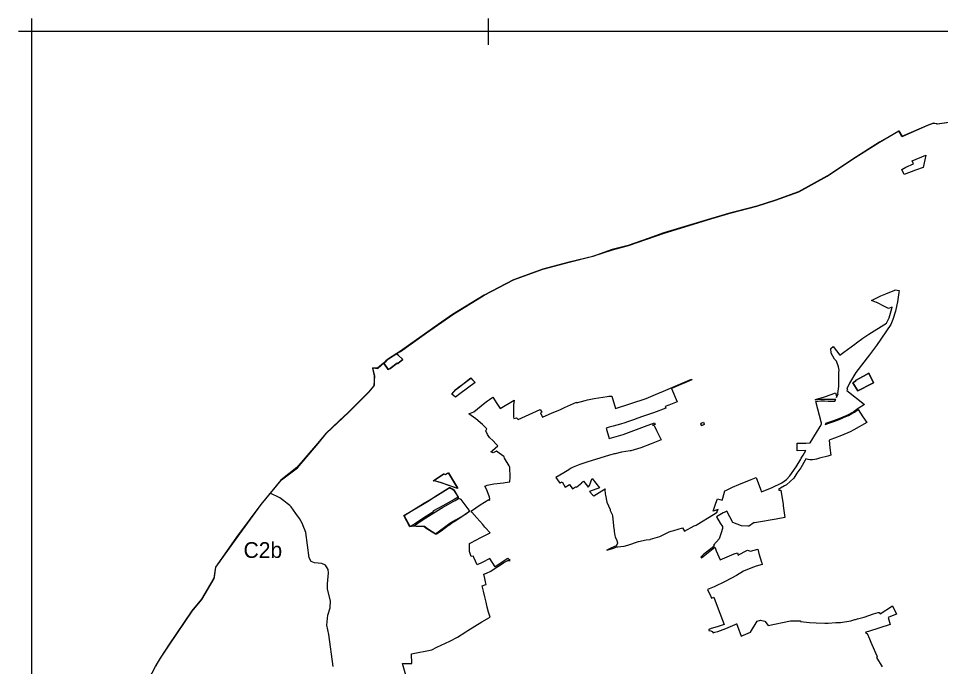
# Model space of a CAD drawing. Extents: x -478490 to -472450, y -1118050 to -1109550.
# Drawn here: x -478490 to -474975, y -1112018 to -1109550 of the extents above; entities that cross this region are included whole.
import ezdxf

# ---------------------------------------------------------------- set-up
doc = ezdxf.new("R2010")
doc.units = 0
for name, color, linetype in [('hranice kú', 7, 'Continuous'), ('Implicitní', 7, 'Continuous'), ('ObPÚ', 7, 'Continuous')]:
    doc.layers.add(name, color=color, linetype=linetype)

msp = doc.modelspace()

# ---------------------------------------------------------------- linework, layer by layer
at = {"layer": 'hranice kú'}
for p, q in [((-475002.4, -1109948.5), (-475022.9, -1109956.5)), ((-474987.2, -1109952.5), (-475002.4, -1109948.5)), ((-474886, -1109937.7), (-474987.2, -1109952.5)), ((-475134, -1109979), (-475207.8, -1110021.5)), ((-475122.4, -1109999.6), (-475134, -1109979)), ((-475022.9, -1109956.5), (-475122.4, -1109999.6)), ((-475207.8, -1110021.5), (-475309.6, -1110086.2)), ((-475309.6, -1110086.2), (-475401.1, -1110146.7)), ((-475408.2, -1110151.3), (-475516.2, -1110210.6)), ((-475401.1, -1110146.7), (-475408.2, -1110151.3)), ((-475516.2, -1110210.6), (-475603.8, -1110242.4)), ((-475675.9, -1110264.8), (-475748.8, -1110283.6)), ((-475603.8, -1110242.4), (-475675.9, -1110264.8)), ((-475774.2, -1110290.1), (-475851.9, -1110313.6)), ((-475748.8, -1110283.6), (-475774.2, -1110290.1)), ((-475851.9, -1110313.6), (-476030.1, -1110367.2)), ((-476030.1, -1110367.2), (-476089.1, -1110387.7)), ((-476089.1, -1110387.7), (-476165.8, -1110414.4)), ((-476226.9, -1110430.6), (-476300.5, -1110456.1)), ((-476165.8, -1110414.4), (-476226.9, -1110430.6)), ((-476390.6, -1110478.9), (-476491.3, -1110505.4)), ((-476300.5, -1110456.1), (-476390.6, -1110478.9)), ((-476491.3, -1110505.4), (-476602.9, -1110545.8)), ((-476602.9, -1110545.8), (-476714.7, -1110603.6)), ((-476714.7, -1110603.6), (-476835.3, -1110677.2)), ((-476835.3, -1110677.2), (-476889.8, -1110715.9)), ((-476889.8, -1110715.9), (-477034.1, -1110817.7)), ((-477047.8, -1110826.2), (-477079.5, -1110846.1)), ((-477034.1, -1110817.7), (-477047.8, -1110826.2)), ((-477098.4, -1110862.6), (-477121, -1110882.3)), ((-477089.2, -1110854.5), (-477098.4, -1110862.6)), ((-477079.5, -1110846.1), (-477089.2, -1110854.5)), ((-477121, -1110882.3), (-477141, -1110882)), ((-477141, -1110882), (-477133.6, -1110911.5)), ((-477134.2, -1110929.3), (-477134.7, -1110947.1)), ((-477133.6, -1110911.5), (-477134.2, -1110929.3)), ((-477155, -1110972.4), (-477210.7, -1111027.9)), ((-477142.3, -1110956.6), (-477155, -1110972.4)), ((-477134.7, -1110947.1), (-477142.3, -1110956.6)), ((-477216.6, -1111033.9), (-477229.4, -1111046.9)), ((-477214.6, -1111031.9), (-477216.6, -1111033.9)), ((-477210.7, -1111027.9), (-477214.6, -1111031.9)), ((-477233.1, -1111050.4), (-477267, -1111082.3)), ((-477229.4, -1111046.9), (-477233.1, -1111050.4)), ((-477267, -1111082.3), (-477317.9, -1111130.4)), ((-477317.9, -1111130.4), (-477350, -1111169.3)), ((-477350, -1111169.3), (-477428.5, -1111260.9)), ((-477428.5, -1111260.9), (-477490.1, -1111308.2)), ((-477490.1, -1111308.2), (-477566.2, -1111401.8)), ((-477566.2, -1111401.8), (-477658.2, -1111526.7)), ((-477658.2, -1111526.7), (-477738.5, -1111640.6)), ((-477738.5, -1111640.6), (-477743.9, -1111676.8)), ((-477745.7, -1111682.6), (-477792.7, -1111763.5)), ((-477743.9, -1111676.8), (-477745.7, -1111682.6)), ((-477792.7, -1111763.5), (-477829.2, -1111807.1)), ((-477829.2, -1111807.1), (-477917, -1111937.1)), ((-477917, -1111937.1), (-477949.4, -1111986.8)), ((-477949.4, -1111986.8), (-477967.8, -1112018.8))]:
    msp.add_line(p, q, dxfattribs=at)
at = {"layer": 'Implicitní'}
for p, q in [((-478440.1, -1109550.1), (-478440.1, -1109650.1)), ((-478440.1, -1109550.1), (-478440.1, -1109650.1)), ((-478440.1, -1109550.1), (-478440.1, -1109650.1)), ((-478440.1, -1109550.1), (-478440.1, -1109650.1)), ((-478440.1, -1109550.1), (-478440.1, -1109650.1)), ((-478440.1, -1109550.1), (-478440.1, -1109650.1)), ((-478440.1, -1109550.1), (-478440.1, -1109650.1)), ((-476700.1, -1109550.1), (-476700.1, -1109650.1)), ((-476700.1, -1109550.1), (-476700.1, -1109650.1)), ((-476700.1, -1109550.1), (-476700.1, -1109650.1)), ((-476700.1, -1109550.1), (-476700.1, -1109650.1)), ((-476700.1, -1109550.1), (-476700.1, -1109650.1)), ((-476700.1, -1109550.1), (-476700.1, -1109650.1)), ((-476700.1, -1109550.1), (-476700.1, -1109650.1)), ((-478390.1, -1109600.1), (-478490.1, -1109600.1)), ((-478390.1, -1109600.1), (-478490.1, -1109600.1)), ((-478390.1, -1109600.1), (-478490.1, -1109600.1)), ((-478390.1, -1109600.1), (-478490.1, -1109600.1)), ((-478390.1, -1109600.1), (-478490.1, -1109600.1)), ((-478390.1, -1109600.1), (-478490.1, -1109600.1)), ((-476650.1, -1109600.1), (-476750.1, -1109600.1)), ((-476650.1, -1109600.1), (-476750.1, -1109600.1)), ((-476650.1, -1109600.1), (-476750.1, -1109600.1)), ((-476650.1, -1109600.1), (-476750.1, -1109600.1)), ((-476650.1, -1109600.1), (-476750.1, -1109600.1)), ((-476650.1, -1109600.1), (-476750.1, -1109600.1))]:
    msp.add_line(p, q, dxfattribs=at)
msp.add_lwpolyline([(-478440.1, -1118000.1), (-472500.1, -1118000.1), (-472500.1, -1109600.1), (-478440.1, -1109600.1)], close=True, dxfattribs=at)
msp.add_lwpolyline([(-477290.1, -1112018.2), (-477307.4, -1111896.5), (-477314.6, -1111861), (-477310.7, -1111823), (-477302.3, -1111794.9), (-477301.2, -1111768), (-477312.4, -1111723.9), (-477312, -1111703.3), (-477307.7, -1111662), (-477309.2, -1111649), (-477319.7, -1111632.3), (-477333.1, -1111626.6), (-477361.3, -1111624.1), (-477373.9, -1111618.6), (-477382.1, -1111604.4), (-477394.5, -1111508.3), (-477396.9, -1111501.8), (-477398.4, -1111497.9), (-477402.6, -1111488.6), (-477408.8, -1111472.3), (-477418.7, -1111455), (-477432.4, -1111435.9), (-477450.9, -1111410.1), (-477455.1, -1111405.5), (-477460.2, -1111401.4), (-477465.7, -1111397.1), (-477478.8, -1111387.9), (-477493.1, -1111376.5), (-477530.1, -1111358.5)], dxfattribs=at)
at = {"layer": 'ObPÚ'}
for p, q in [((-476749.5, -1110936), (-476807.4, -1110979.7)), ((-476795.8, -1110942.9), (-476765.1, -1110919.2)), ((-476765.1, -1110919.2), (-476749.5, -1110936)), ((-476838.6, -1110980.4), (-476823.6, -1110964)), ((-476823.6, -1110964), (-476813.4, -1110956.5)), ((-476813.4, -1110956.5), (-476795.8, -1110942.9)), ((-476823.5, -1110992.3), (-476838.6, -1110980.4)), ((-476807.4, -1110979.7), (-476823.5, -1110992.3)), ((-476909, -1111310.7), (-476870.1, -1111284.8)), ((-476870.1, -1111284.8), (-476863.3, -1111287.6)), ((-476863.3, -1111287.6), (-476852.1, -1111280.5)), ((-476852.1, -1111280.5), (-476817.4, -1111337.3)), ((-476900.7, -1111312.2), (-476909, -1111310.7)), ((-476891.2, -1111315.2), (-476900.7, -1111312.2)), ((-476878.5, -1111319.2), (-476891.2, -1111315.2)), ((-476816.7, -1111340.2), (-476878.5, -1111319.2)), ((-476817.4, -1111337.3), (-476816.7, -1111340.2))]:
    msp.add_line(p, q, dxfattribs=at)
for points in [[(-477992.6, -1112066.4), (-477967.7, -1112017.9), (-477949, -1111986), (-477916, -1111936), (-477827.8, -1111806.6), (-477791.1, -1111762.3), (-477744.4, -1111681.6), (-477737.4, -1111639.5), (-477657.3, -1111525.4), (-477565.5, -1111400.8), (-477486.9, -1111307), (-477426, -1111261.1), (-477348, -1111168.5), (-477315.2, -1111130.2), (-477231.4, -1111050.6), (-477154.2, -1110973.6), (-477134.2, -1110948.8), (-477133.2, -1110930.3), (-477132.1, -1110911.9), (-477138.9, -1110881.3), (-477119.7, -1110882.7), (-477097.2, -1110862.7), (-477080.6, -1110886.8), (-477072.5, -1110883.8), (-477045.9, -1110863.6), (-477043.9, -1110864.1), (-477025.3, -1110849.6), (-477043.5, -1110830.7), (-477047.5, -1110826.1), (-477033.7, -1110818.2), (-476934, -1110747.9), (-476834.4, -1110677.8), (-476714.6, -1110603.8), (-476602.9, -1110545.9), (-476491.3, -1110505.5), (-476390.2, -1110478.8), (-476300.7, -1110455.7), (-476225.2, -1110430.7), (-476164.4, -1110414.7), (-476028.4, -1110367.7), (-475850.6, -1110313.7), (-475773.2, -1110290.1), (-475675.4, -1110264.4), (-475603.9, -1110241.6), (-475515.6, -1110210.1), (-475407.7, -1110150.6), (-475310.4, -1110085.4), (-475208.2, -1110020.8), (-475134, -1109978.4), (-475121.9, -1109999.1), (-475023.6, -1109956.4), (-475002.8, -1109948.9), (-474998, -1109949.5), (-474990.2, -1109950.6), (-474989.1, -1109950.8), (-474987.5, -1109951), (-474886.4, -1109937.2)], [(-475031.6, -1110070.7), (-475035.2, -1110088.3), (-475041.6, -1110117.3), (-475071, -1110128.2), (-475113.6, -1110143.8), (-475122.4, -1110125.3), (-475107.2, -1110116.9), (-475078.7, -1110104.2), (-475082.7, -1110091.8), (-475031.6, -1110070.7)], [(-475148.1, -1110584.1), (-475132.8, -1110586.1), (-475134.1, -1110594.3), (-475139.6, -1110629.2), (-475141.4, -1110640.6), (-475147, -1110664.5), (-475156.6, -1110696.8), (-475164.7, -1110715.7), (-475219.8, -1110795.7), (-475246.4, -1110830.8), (-475297.9, -1110899.1), (-475322.5, -1110939.2), (-475323.4, -1110941.1), (-475326.2, -1110947.8), (-475332.4, -1110960.1), (-475329.7, -1110962.2), (-475332.8, -1110966.5), (-475264.7, -1111020.3), (-475289.6, -1111035.6), (-475304.6, -1111046.6), (-475313.5, -1111051.8), (-475327.3, -1111059.4), (-475332.9, -1111062), (-475368.8, -1111077.8), (-475390.2, -1111085.2), (-475413.5, -1111093), (-475413.9, -1111095.5), (-475414.6, -1111096.5), (-475396.8, -1111090.7), (-475381.9, -1111085.4), (-475368.1, -1111080.4), (-475352.2, -1111073.9), (-475342, -1111069.3), (-475326, -1111062.1), (-475313, -1111054.8), (-475303.1, -1111049.2), (-475289.4, -1111039.2), (-475271.1, -1111067.1), (-475256.4, -1111089.3), (-475305.6, -1111116.7), (-475319, -1111124.5), (-475352.1, -1111139), (-475379.3, -1111149.1), (-475393.3, -1111153.4), (-475400.3, -1111156), (-475396.5, -1111185.4), (-475392.7, -1111213), (-475404.3, -1111216.8), (-475436.9, -1111225.3), (-475448.5, -1111228.4), (-475454.5, -1111229.6), (-475463.7, -1111230.8), (-475472.8, -1111231.1), (-475479.9, -1111230.5), (-475488.1, -1111228), (-475488.8, -1111227.8), (-475491.2, -1111232.3), (-475508.3, -1111261.2), (-475522.4, -1111282.1), (-475534.8, -1111300.6), (-475562.6, -1111326.6), (-475569.6, -1111330.7), (-475585.2, -1111339.6), (-475592.6, -1111343.6), (-475588.6, -1111346.6), (-475584.2, -1111346.5), (-475575.5, -1111400.7), (-475574.6, -1111407), (-475568.6, -1111450.4), (-475601.1, -1111456.6), (-475624.5, -1111461.2), (-475654.2, -1111466.4), (-475684.3, -1111471.3), (-475687.2, -1111470.6), (-475693.7, -1111474.8), (-475699, -1111480.1), (-475705.7, -1111483.9), (-475709.8, -1111483.9), (-475733.4, -1111483.1), (-475767, -1111469.8), (-475790, -1111426.6), (-475799.8, -1111431.5), (-475804, -1111433.4), (-475810.7, -1111436.7), (-475829.7, -1111448), (-475814.9, -1111472), (-475806.3, -1111484.8), (-475806.3, -1111493.2), (-475811.6, -1111509.7), (-475812.7, -1111512.9), (-475812.9, -1111513.5), (-475819.1, -1111532.4), (-475841.2, -1111555.7), (-475838.5, -1111560.3), (-475845.9, -1111566.1), (-475877.4, -1111590.5)], [(-475218.2, -1110632.5), (-475219.5, -1110631.9), (-475238.7, -1110624.8), (-475202.4, -1110607.1), (-475184, -1110598.8), (-475149.9, -1110584.6), (-475148.1, -1110584.1)], [(-476080.7, -1111533.9), (-476044.6, -1111522.8), (-476009.2, -1111505.3), (-476006, -1111504.3), (-476001.7, -1111502.9), (-475992.1, -1111500.1), (-475958.5, -1111489.8), (-475951, -1111502.6), (-475913.8, -1111482.5), (-475907.2, -1111479.6), (-475903.4, -1111477.7), (-475840.3, -1111439.7), (-475827.1, -1111429.9), (-475826.5, -1111427.2), (-475822.6, -1111420.1), (-475841.5, -1111426.4), (-475831.2, -1111395.6), (-475825.9, -1111379.1), (-475807.2, -1111385.2), (-475804.9, -1111377.5), (-475797.7, -1111349), (-475791.1, -1111346.2), (-475768.3, -1111335.9), (-475744.5, -1111325.5), (-475728.4, -1111319.2), (-475712.4, -1111312.7), (-475696.6, -1111306.6), (-475678, -1111299.1), (-475661.4, -1111342.5), (-475657.5, -1111352.7), (-475617.2, -1111336.5), (-475580, -1111319.1), (-475562.6, -1111305.8), (-475549.8, -1111292.6), (-475525.8, -1111258.2), (-475508.2, -1111228.6), (-475505.8, -1111225), (-475499.2, -1111213), (-475489.2, -1111195.3), (-475521.1, -1111196.7), (-475521.1, -1111167.4), (-475509.5, -1111167.4), (-475488.5, -1111167.2), (-475472.4, -1111166.6), (-475447.9, -1111126.5), (-475434.6, -1111104.4), (-475428.9, -1111094.7), (-475429.3, -1111091.8), (-475450.3, -1111008.5), (-475431.9, -1111006.9), (-475417.8, -1111006.3), (-475403.1, -1111007.2), (-475398.3, -1111007.7), (-475379.8, -1111008.2), (-475378.3, -1111008.3), (-475374.8, -1111001.4), (-475389.4, -1111001.4), (-475396.2, -1111001.5), (-475432.4, -1111001.7), (-475451.6, -1111003.6), (-475452.3, -1111000.8), (-475417.3, -1110991.5), (-475392.6, -1110982.3), (-475375.7, -1110975.9), (-475373.5, -1110983.9), (-475371.1, -1110993.9), (-475364.9, -1110979.2), (-475366.7, -1110978.5), (-475362.9, -1110952.1), (-475362.8, -1110931.7), (-475362.6, -1110916.2), (-475362.9, -1110905.9), (-475363, -1110901.2), (-475363, -1110898.2), (-475361.8, -1110890.2), (-475364.3, -1110877.5), (-475372.3, -1110855.4), (-475379.1, -1110847.3), (-475391.9, -1110824.9), (-475393.8, -1110806.5), (-475383.9, -1110799.9), (-475359.1, -1110832.8), (-475343.3, -1110821.2), (-475301.6, -1110790.1), (-475295.5, -1110785.5), (-475271.4, -1110767.5), (-475248.6, -1110752.7), (-475181.1, -1110710.8), (-475171.1, -1110690.7), (-475163.2, -1110663.4), (-475159.1, -1110649.7), (-475173.1, -1110654.9), (-475181, -1110650.7), (-475198.3, -1110641.7), (-475207.7, -1110637.2), (-475218.2, -1110632.5)], [(-477047.5, -1110826.1), (-477043.5, -1110830.7), (-477025.3, -1110849.6), (-477043.9, -1110864.1), (-477045.9, -1110863.6), (-477072.5, -1110883.8), (-477080.6, -1110886.8), (-477097.2, -1110862.7), (-477088.2, -1110854.8), (-477078.9, -1110846), (-477062.1, -1110835), (-477047.5, -1110826.1)], [(-476765.5, -1110919.5), (-476749.7, -1110936.3), (-476807.4, -1110980.3), (-476823.5, -1110992.5), (-476838.5, -1110980.6), (-476823.2, -1110963.8), (-476813.4, -1110956.1), (-476796, -1110942.8), (-476765.5, -1110919.5)], [(-476755.5, -1111599), (-476755.8, -1111598), (-476764.4, -1111599.6), (-476770.5, -1111580.2), (-476771, -1111565.2), (-476770.2, -1111549.7), (-476741.8, -1111534.8), (-476732, -1111529.7), (-476696.8, -1111511.7), (-476692.5, -1111509.2), (-476710.4, -1111489.4), (-476712.4, -1111487.1), (-476720, -1111478.1), (-476742.3, -1111451.6), (-476761.2, -1111430.1), (-476764.4, -1111426.4), (-476763, -1111425.6), (-476729.7, -1111402.9), (-476697.2, -1111382.4), (-476694.7, -1111386.2), (-476693.6, -1111380.2), (-476694.2, -1111372.8), (-476699.2, -1111358.8), (-476706, -1111342.3), (-476712.2, -1111331.2), (-476708.5, -1111329.6), (-476702.9, -1111327.4), (-476678.2, -1111323.1), (-476641.2, -1111318.6), (-476634.7, -1111317.8), (-476617.1, -1111314.8), (-476616.1, -1111297.4), (-476616.8, -1111259.6), (-476619.4, -1111254.6), (-476636.7, -1111224.2), (-476638.2, -1111219.2), (-476639.6, -1111217.9), (-476648.1, -1111211.8), (-476657.2, -1111205.2), (-476667.7, -1111197.8), (-476668.1, -1111197.6), (-476680.6, -1111204.3), (-476688.9, -1111200.3), (-476683.5, -1111195.6), (-476662.2, -1111177.8), (-476669.9, -1111169.8), (-476680.8, -1111158.9), (-476694.9, -1111146.1), (-476702.3, -1111134.6), (-476708.2, -1111120.9), (-476704.6, -1111113.1), (-476707.2, -1111110.4), (-476710.6, -1111106.8), (-476721, -1111096.9), (-476747.1, -1111075.5), (-476773.1, -1111056.3), (-476753.8, -1111047.8), (-476712.6, -1111014.6), (-476702.4, -1111006.3), (-476694.3, -1111001.1), (-476681.6, -1110992.9), (-476666.8, -1111016), (-476654.4, -1111035.6), (-476600.8, -1111004.3), (-476602.7, -1111021.1), (-476603.2, -1111049.6), (-476602.9, -1111060), (-476603.3, -1111068.5), (-476602.2, -1111073.2), (-476591.8, -1111071.3), (-476584.8, -1111077.5), (-476501, -1111039.4), (-476495.6, -1111050.2), (-476500.4, -1111052.6), (-476492.4, -1111068.6), (-476455.9, -1111052.7), (-476446, -1111048.3), (-476423.8, -1111038.9), (-476408.7, -1111032.4), (-476362.8, -1111011.5), (-476363.1, -1111014.2), (-476329.8, -1111004.9), (-476321.4, -1111003.2), (-476295.6, -1110998.1), (-476262.7, -1110992.2), (-476245.3, -1110989.6), (-476239, -1110988.4), (-476229.4, -1110989.3), (-476228.4, -1110989.3), (-476213.9, -1111036.2), (-476097.8, -1110998.2), (-476044, -1110974.6), (-476040.4, -1110973.1), (-475923.9, -1110923.8), (-475922.9, -1110926.6), (-476001.2, -1110960.1)], [(-476001.2, -1110960.1), (-475978.5, -1111010.4), (-476010.9, -1111022.5), (-476024.9, -1111027.8), (-476022.1, -1111034.1), (-476068.7, -1111052.3), (-476114.9, -1111067.7), (-476138.6, -1111076), (-476141.9, -1111077.2), (-476168.5, -1111086.4), (-476178.6, -1111089.9), (-476195.4, -1111094.7), (-476223, -1111102.6), (-476238.7, -1111107), (-476249.6, -1111110.1), (-476237.8, -1111150.3), (-476184.5, -1111134.3), (-476103.8, -1111104.7), (-476065.3, -1111090.1), (-476062.5, -1111096.4), (-476072.5, -1111099), (-476067.4, -1111100.8), (-476057.5, -1111119.9), (-476052.6, -1111129.4), (-476039.5, -1111154.8), (-476078.4, -1111169.8), (-476117, -1111185.5), (-476155.8, -1111197), (-476158.1, -1111197.3), (-476191.7, -1111201.9), (-476214.9, -1111207.7), (-476217.9, -1111208.5), (-476236.6, -1111213.2), (-476323, -1111239.7), (-476350.1, -1111249), (-476375, -1111259), (-476385.9, -1111264.8), (-476392.2, -1111269.7), (-476411, -1111280.8), (-476441.4, -1111298.3), (-476428.9, -1111316.6), (-476426.7, -1111320.2), (-476425.5, -1111319.4), (-476418.1, -1111314.4), (-476406.1, -1111334.8), (-476390, -1111324.6), (-476377.8, -1111342), (-476366.1, -1111333.4), (-476364.4, -1111335.6), (-476361.5, -1111333.8), (-476342.9, -1111319.2), (-476343.8, -1111317.9), (-476335.7, -1111311.8), (-476321.2, -1111332.1), (-476318.9, -1111334.9), (-476313, -1111328.6), (-476309.8, -1111318.6), (-476305.3, -1111306.9), (-476302.5, -1111302), (-476275.6, -1111337.5), (-476313.2, -1111352.2), (-476300.2, -1111365.6), (-476297.2, -1111368.2), (-476265.8, -1111348.7), (-476253.2, -1111341.5), (-476254.2, -1111345.1), (-476254.1, -1111360.3), (-476252.9, -1111365.5), (-476247.1, -1111391.9), (-476235, -1111420.9), (-476233.9, -1111423.6), (-476227.1, -1111439.9), (-476225.4, -1111444.4), (-476220, -1111494.3), (-476219.8, -1111496.3), (-476219.6, -1111498.6), (-476218.9, -1111504.2), (-476216.5, -1111519.8), (-476214.9, -1111524.1), (-476208.9, -1111538.8), (-476206.5, -1111547), (-476206.4, -1111550.3), (-476211.4, -1111559.3), (-476232.4, -1111567.1), (-476247.2, -1111575.1), (-476229.9, -1111569.6), (-476218.5, -1111566.3), (-476210.1, -1111562.7), (-476205.2, -1111562.3), (-476193.3, -1111561.9), (-476181.7, -1111559.9), (-476167.6, -1111555.9), (-476126.1, -1111541.6), (-476097.4, -1111535.9), (-476082.4, -1111534.1), (-476080.7, -1111533.9)], [(-475878.6, -1111087.3), (-475875.6, -1111094.7), (-475876.6, -1111095.2), (-475876.2, -1111096.1), (-475875.8, -1111097), (-475885.9, -1111101.2), (-475886.3, -1111100.2), (-475888.6, -1111093.7), (-475887, -1111093.1), (-475887.8, -1111091.1), (-475878.6, -1111087.3)], [(-476851.2, -1111280.9), (-476816.7, -1111337.6), (-476815.9, -1111340.5), (-476877.8, -1111319.3), (-476890.3, -1111315.3), (-476899.7, -1111312.3), (-476908, -1111310.6), (-476869, -1111284.9), (-476862.3, -1111287.4), (-476851.2, -1111280.9)], [(-476845.8, -1111336.8), (-476833.2, -1111343.1), (-476830.3, -1111345.2), (-476814.1, -1111373.4), (-476829.7, -1111382.6), (-476871.8, -1111406), (-476907.9, -1111425.4), (-476911.4, -1111431), (-476914.7, -1111433.2), (-476935, -1111446.2), (-476979.5, -1111474.5), (-476996.8, -1111485.2), (-477019.2, -1111443.1), (-476956.1, -1111404.4), (-476941.7, -1111395.5), (-476928.8, -1111387.7), (-476892.8, -1111365.7), (-476851.6, -1111340.4), (-476845.8, -1111336.8)], [(-476810.1, -1111378.3), (-476805.9, -1111379.4), (-476804.7, -1111380.3), (-476803.4, -1111382.1), (-476792.3, -1111397.6), (-476773.7, -1111423.2), (-476770.2, -1111428.1), (-476787.4, -1111439.3), (-476804.2, -1111450.6), (-476823.1, -1111463.3), (-476837.9, -1111472.8), (-476847.1, -1111479.5), (-476850.6, -1111481.9), (-476879.3, -1111502.4), (-476896.2, -1111514.4), (-476899, -1111514.2), (-476930.7, -1111494), (-476942.5, -1111485.1), (-476965.9, -1111485.2), (-476984.4, -1111483.5), (-476947.9, -1111458.3), (-476916.7, -1111438.9), (-476890.7, -1111423.1), (-476880.5, -1111416.9), (-476873.4, -1111412.5), (-476851.1, -1111400.2), (-476833, -1111390.3), (-476824.8, -1111385.7), (-476813, -1111378.7), (-476810.1, -1111378.3)], [(-475877.4, -1111590.5), (-475888.6, -1111601.4), (-475886, -1111604.2), (-475836, -1111564.4), (-475833.6, -1111570.2), (-475830.2, -1111577.9), (-475814.8, -1111612), (-475761.7, -1111589.4), (-475749.3, -1111584.9), (-475746.8, -1111594.7), (-475738, -1111589.5), (-475721.7, -1111579.9), (-475710.7, -1111575.7), (-475699.7, -1111579.1), (-475672.1, -1111571.2), (-475667.3, -1111587.5), (-475657.2, -1111621.4), (-475656.6, -1111623.4), (-475654.6, -1111630.4), (-475677.9, -1111636.7), (-475698.4, -1111643.4), (-475726.3, -1111654.9), (-475753.2, -1111671.8), (-475796.4, -1111694.5), (-475838.6, -1111714.6), (-475863.6, -1111725.3), (-475850.8, -1111752.1), (-475848.8, -1111757.6), (-475839.8, -1111754), (-475822.7, -1111798.9), (-475799.8, -1111858.4), (-475826.7, -1111867.4), (-475849.1, -1111873.9), (-475859, -1111876.8), (-475858.5, -1111881.8), (-475850.5, -1111882.4), (-475846, -1111885.5), (-475841.5, -1111890.5), (-475835.8, -1111887.6), (-475824.7, -1111884.4), (-475793.6, -1111873.2), (-475757.8, -1111858.6), (-475752.6, -1111855.2), (-475751.9, -1111856.2), (-475751.3, -1111858.9), (-475749.1, -1111864.3), (-475735.2, -1111903), (-475699, -1111887), (-475673.7, -1111845.3), (-475661.5, -1111842.2), (-475645.4, -1111845.7), (-475632.5, -1111862.8), (-475547.6, -1111845), (-475509.3, -1111844.8), (-475509.4, -1111846.9), (-475475.1, -1111850.7), (-475449.8, -1111852.2), (-475416.4, -1111853.9), (-475403.4, -1111853.3), (-475374.7, -1111851.3), (-475356.5, -1111850.4), (-475317.7, -1111843.9), (-475302.2, -1111839.9), (-475298.9, -1111839.2), (-475291.5, -1111836.7), (-475266.1, -1111830), (-475230.2, -1111817.8), (-475212.6, -1111813.1), (-475209, -1111812.4), (-475205, -1111817.9), (-475157.9, -1111786.7), (-475143.1, -1111818.7), (-475171.7, -1111830.3), (-475175.1, -1111831.6), (-475166.6, -1111858.8), (-475250, -1111885.1), (-475260.4, -1111887.5), (-475261.4, -1111889.2), (-475254.8, -1111892.9), (-475246.3, -1111913), (-475243.5, -1111919.3), (-475240.6, -1111926), (-475236.6, -1111935), (-475217.4, -1111978.1), (-475216.4, -1111980.6), (-475219.2, -1111983.5), (-475197.7, -1112019.3)], [(-477007.9, -1112069), (-477025.9, -1112007.4), (-476990.5, -1112007), (-476992.4, -1111969.7), (-476913.9, -1111954.4), (-476895, -1111945), (-476846.1, -1111921.6), (-476816.5, -1111906.9), (-476785, -1111886.7), (-476776.6, -1111881.3), (-476750.7, -1111864.8), (-476724.3, -1111848.2), (-476695, -1111831.9), (-476691.4, -1111829.9), (-476697.9, -1111811.9), (-476703.4, -1111792.7), (-476707.7, -1111773.2), (-476712.7, -1111753.4), (-476717.9, -1111731.2), (-476718.9, -1111726.7), (-476722.5, -1111711.7), (-476708, -1111706.3), (-476706.6, -1111705.8), (-476709.3, -1111696.3), (-476712.4, -1111683.4), (-476716.3, -1111667), (-476706.5, -1111662.8), (-476689.2, -1111655), (-476672.4, -1111644.1), (-476656.2, -1111633.3), (-476639.8, -1111622.5), (-476624.6, -1111614.3), (-476615.7, -1111614.8), (-476624, -1111606.8), (-476672.6, -1111638.9), (-476693.6, -1111607.2), (-476722.7, -1111621.8), (-476740.9, -1111630.8), (-476754.6, -1111602.9), (-476755.5, -1111599)]]:
    msp.add_lwpolyline(points, dxfattribs=at)
for points in [[(-475309.6, -1110937.3), (-475298.3, -1110930.6), (-475298.9, -1110929.2), (-475268.3, -1110911.9), (-475249.1, -1110901.1), (-475230.6, -1110937.3), (-475253.9, -1110949.2), (-475272, -1110958.9), (-475280.6, -1110963.6), (-475290, -1110968.6)], [(-475309.6, -1110937.3), (-475290, -1110968.6), (-475280.6, -1110963.6), (-475272, -1110958.9), (-475253.9, -1110949.2), (-475230.6, -1110937.3), (-475249.1, -1110901.1), (-475268.3, -1110911.9), (-475298.9, -1110929.2), (-475298.3, -1110930.6)], [(-476847.1, -1111336.5), (-476831.3, -1111345), (-476814.5, -1111373.1), (-476813.5, -1111378.5), (-476810.5, -1111378.2), (-476806.2, -1111379.8), (-476803.9, -1111382.7), (-476792.3, -1111397.2), (-476773, -1111422.4), (-476769.2, -1111426.6), (-476786.4, -1111438.9), (-476824.6, -1111461), (-476839.5, -1111469.7), (-476846, -1111473.3), (-476899.9, -1111514.2), (-476935.6, -1111492.1), (-476945.3, -1111484.7), (-476973.5, -1111485.2), (-476986, -1111484.2), (-476998.5, -1111486), (-477020.9, -1111443.5), (-476943, -1111397.1), (-476931.4, -1111390.2), (-476893.5, -1111366.1), (-476853.3, -1111340.3)]]:
    msp.add_lwpolyline(points, close=True, dxfattribs=at)

# ---------------------------------------------------------------- texts
at = {"layer": 'Implicitní'}
msp.add_text('C2b', height=60, dxfattribs=at).set_placement((-477632, -1111604.7))

doc.saveas('drawing.dxf')
